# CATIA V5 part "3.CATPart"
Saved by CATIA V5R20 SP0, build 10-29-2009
Part number: poussoir 3
Bounding box of the stored display mesh (mm): x 205 to 215, y 192.296 to 385, z 0 to 15
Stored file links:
  C:\Users\Willy\Documents\ThinkMotion\1691\3.CATPart
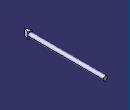
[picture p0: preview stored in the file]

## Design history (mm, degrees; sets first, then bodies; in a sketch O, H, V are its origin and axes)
Body1 (main body)
  Sketch1 on xy-plane, origin (0, 0, 0), H (1, 0, 0), V (0, 1, 0)
    line L1 (205, 205) -> (210, 200)
    point P2 (210, 200)
    line L2 (210, 200) -> (215, 205)
    line L3 (215, 205) -> (205, 205)
    axis line L4 (210, 250) -> (210, 230)
    angle L2 L1 = 90
    distance P2 L3 = 5
    horizontal: L3 H
    vertical: L4 V
    symmetry: L1 L2 L4
  Pad1: profile Sketch1, direction (0, 0, 1), length 15
  Sketch2 on face of Pad1 from Sketch1.L3, origin (0, 205, 0), H (-1, 0, 0), V (0, 0, 1)
    circle A1 centre (-210, 7.5) radius 5
    point P1 (-210, 7.5)
    reference projected line E1 (-215, 0) -> (-215, 15) from edge [face of Pad1 from Sketch1.L3 | face of Pad1 from Sketch1.L2]
    reference projected line E2 (-205, 0) -> (-205, 15) from edge [face of Pad1 from Sketch1.L1 | face of Pad1 from Sketch1.L3]
    reference projected line E3 (-215, 0) -> (-205, 0) from edge [start face of Pad1 | face of Pad1 from Sketch1.L3]
    reference projected line E4 (-215, 15) -> (-205, 15) from edge [face of Pad1 from Sketch1.L3 | end face of Pad1]
    radius A1 = 5
    equidistance: E1 E2 P1, E3 E4 P1
  Pad2: profile Sketch2, direction (0, 1, 0), length 180
  Sketch3 on end face of Pad1, origin (0, 0, 15), H (1, 0, 0), V (0, 1, 0)
    line L1 (143.6075, 200.5) -> (220, 200.5)
    line L2 (220, 200.5) -> (220, 200)
    line L3 (220, 200) -> (143.6075, 200)
    line L4 (143.6075, 200) -> (143.6075, 200.5)
    reference projected point E1 (210, 200) from vertex [face of Pad1 from Sketch1.L2 | end face of Pad1 | face of Pad1 from Sketch1.L1]
    length L2 = 0.5
    horizontal: L1 H, L3 H
    vertical: L2 V, L4 V
    coincidence: L3 E1
  Pocket1: profile Sketch3, direction (0, 0, -1), length 15
  DatumCurve1
  Sketch4 on end face of Pad1, origin (0, 0, 15), H (1, 0, 0), V (0, 1, 0)
    point P1 (209.5, 200.5)
    line L1 (209.5, 200.5) -> (210.5, 200.5)
    point P2 (210.5, 200.5)
    line L2 (210.5, 200.5) -> (210, 200)
    point P3 (210, 200)
    line L3 (210, 200) -> (209.5, 200.5)
    reference projected point E1 (210.5, 200.5) from vertex [face of Pad1 from Sketch1.L2 | face of Pocket1 from Sketch3.L1 | end face of Pad1]
    reference projected point E2 (209.5, 200.5) from vertex [face of Pad1 from Sketch1.L1 | face of Pocket1 from Sketch3.L1 | end face of Pad1]
    angle L3 L2 = 90
    horizontal: L1 H
    coincidence: E1 P2, E2 P1
    equidistance: P1 P2 P3
  Pad3: profile Sketch4, direction (0, 0, -1), length 15
  DatumSurface1 to DatumSurface4
  DatumCurve2 to DatumCurve5
  DatumSurface5
  Sketch5 on face of DatumSurface4, origin (0, 0, 15), H (1, 0, 0), V (0, 1, 0)
    line L1 (205, 205) -> (215, 205)
    line L2 (215, 205) -> (210, 192.2961)
    point P3 (210, 192.2961)
    line L3 (210, 192.2961) -> (205, 205)
    reference projected line E1 (215, 205) -> (205, 205) from edge [face of Pad1 from Sketch1.L3 | face of Pad3]
    axis line L4 (210, 220) -> (210, 210)
    reference projected line E2 through (210, 0) direction (0, 1) from axis of face of Pad2 from Sketch2.A1
    reference projected curve E3 from edge of DatumCurve5
    length L1 = 10
    coincidence: L1 E1, E2 L4, P3 E3
    vertical: L4 V
    symmetry: L3 L2 L4
  Pad4: profile Sketch5, direction (0, 0, -1), length 15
